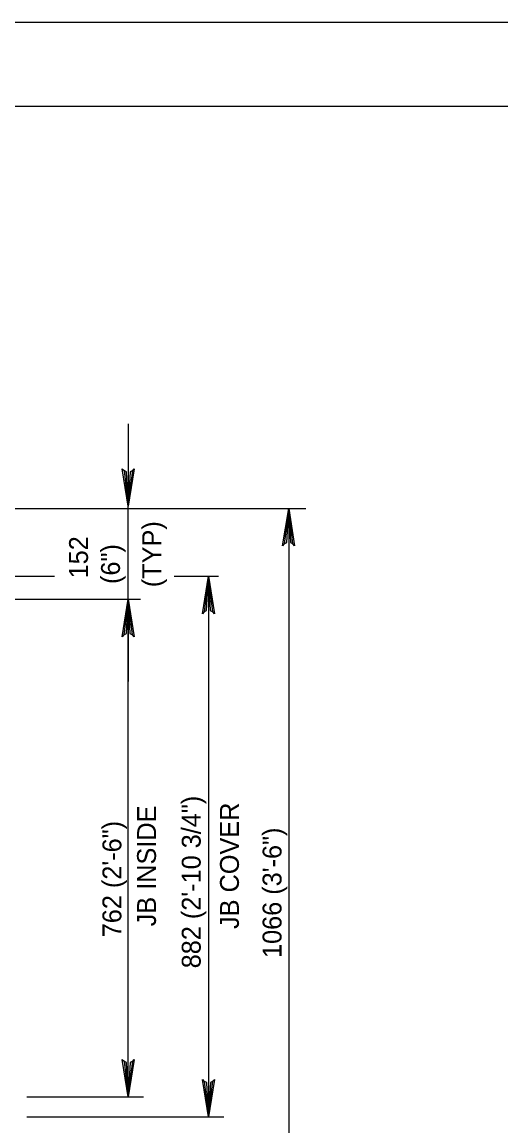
# Model space of a CAD drawing. Extents: x 638455 to 640199, y 298558 to 299152.
# Drawn here: x 639600 to 639685, y 298956 to 299152.2 of the extents above; entities that cross this region are included whole.
import ezdxf

# ---------------------------------------------------------------- set-up
doc = ezdxf.new("R2010")
doc.units = 0
for name, color, linetype in [('1', 7, 'Continuous'), ('2', 7, 'Continuous'), ('3', 7, 'Continuous'), ('PLT-BNDY', 7, 'Continuous')]:
    doc.layers.add(name, color=color, linetype=linetype)

msp = doc.modelspace()

# ---------------------------------------------------------------- linework, layer by layer
at = {"layer": '1'}
msp.add_lwpolyline([(640119.61, 298573.25), (640119.61, 299137.25), (639333.61, 299137.25), (639333.61, 298573.25), (640119.61, 298573.25), (640119.61, 298599.61), (639919.61, 298599.61), (639919.61, 298664.29), (640119.61, 298664.29), (640119.61, 298693.25), (639919.61, 298693.25), (639919.61, 298573.25), (639998.42, 298573.25), (639998.42, 298599.61), (639998.42, 298573.25), (640075.42, 298573.25), (640075.42, 298599.61), (640075.42, 298587.29), (640119.61, 298587.29)], dxfattribs=at)
at = {"layer": '2'}
for p, q in [((639618.83, 299080.83), (639618.83, 299066.19)), ((639547.06, 299065.79), (639650.39, 299065.79)), ((639618.83, 298961.18), (639618.83, 299066.19)), ((639647.33, 299065.79), (639647.33, 298945.42)), ((639535.59, 299053.73), (639605.72, 299053.73)), ((639626.97, 299053.73), (639634.85, 299053.73)), ((639633.08, 299053.73), (639633.08, 298957.61)), ((639529.86, 299049.64), (639621, 299049.64)), ((639618.83, 299049.64), (639618.83, 299035)), ((639600.79, 298961.18), (639621.55, 298961.18)), ((639600.79, 298957.61), (639635.81, 298957.61))]:
    msp.add_line(p, q, dxfattribs=at)
for points in [[(639619.62, 299072.52), (639619.17, 299072.28), (639618.83, 299066.19), (639619.62, 299072.52), (639619.9, 299072.84), (639618.83, 299066.19), (639618.53, 299072.28), (639618.07, 299072.5), (639618.83, 299066.19), (639617.77, 299072.84), (639618.07, 299072.5)], [(639646.53, 299059.46), (639646.99, 299059.7), (639647.33, 299065.79), (639646.53, 299059.46), (639646.25, 299059.14), (639647.33, 299065.79), (639647.63, 299059.7), (639648.08, 299059.48), (639647.33, 299065.79), (639648.38, 299059.14), (639648.08, 299059.48)], [(639632.28, 299047.4), (639632.74, 299047.63), (639633.08, 299053.73), (639632.28, 299047.4), (639632, 299047.07), (639633.08, 299053.73), (639633.38, 299047.64), (639633.83, 299047.42), (639633.08, 299053.73), (639634.14, 299047.07), (639633.83, 299047.42)], [(639618.04, 299043.31), (639618.49, 299043.54), (639618.83, 299049.64), (639618.04, 299043.31), (639617.76, 299042.98), (639618.83, 299049.64), (639619.13, 299043.55), (639619.58, 299043.33), (639618.83, 299049.64), (639619.89, 299042.98), (639619.58, 299043.33)], [(639619.62, 298967.5), (639619.17, 298967.27), (639618.83, 298961.18), (639619.62, 298967.5), (639619.9, 298967.83), (639618.83, 298961.18), (639618.53, 298967.26), (639618.07, 298967.49), (639618.83, 298961.18), (639617.77, 298967.83), (639618.07, 298967.49)], [(639633.87, 298963.94), (639633.41, 298963.71), (639633.08, 298957.61), (639633.87, 298963.94), (639634.15, 298964.27), (639633.08, 298957.61), (639632.78, 298963.7), (639632.32, 298963.92), (639633.08, 298957.61), (639632.02, 298964.27), (639632.32, 298963.92)]]:
    msp.add_lwpolyline(points, dxfattribs=at)
at = {"layer": 'PLT-BNDY'}
msp.add_lwpolyline([(639295.61, 299152.25), (640136.61, 299152.25), (640136.61, 298558.25), (639295.61, 298558.25)], close=True, dxfattribs=at)

# ---------------------------------------------------------------- texts
at = {"layer": '3'}
for s, p in [('(TYP)', (639624.67, 299051.78)), ('152', (639611.67, 299053.34)), ('(6")', (639617.35, 299052.35)), ('882 (2\'-10 3/4")', (639631.69, 298984.02)), ('JB INSIDE', (639623.75, 298991.49)), ('JB COVER', (639638.48, 298991.02)), ('762 (2\'-6")', (639617.6, 298989.54)), ('1066 (3\'-6")', (639646.05, 298985.86))]:
    msp.add_text(s, height=3.36, rotation=90, dxfattribs=at).set_placement(p)

doc.saveas('drawing.dxf')
